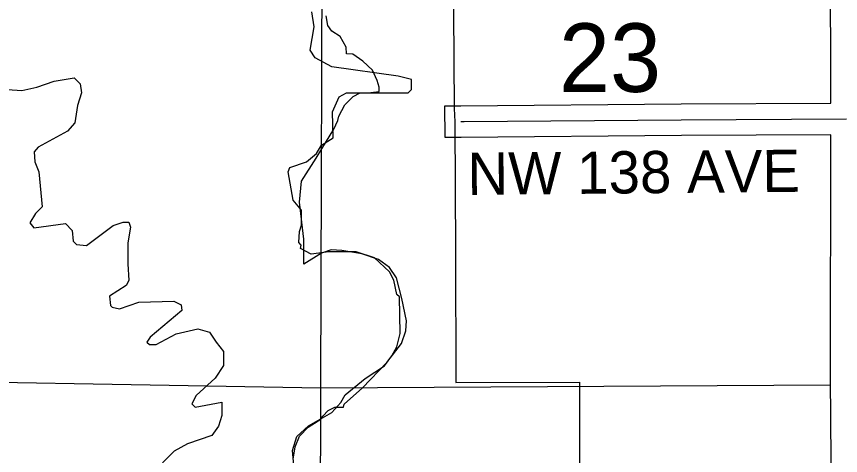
# Model space of a CAD drawing. Extents: x -1403959 to 81668, y -1400582 to 11018.
# Drawn here: x 6553.7 to 6704.7, y 9689.2 to 9769.7 of the extents above; entities that cross this region are included whole.
import ezdxf

# ---------------------------------------------------------------- set-up
doc = ezdxf.new("R2010")
doc.units = 0
for name, color, linetype in [('tdCiMapFrame', 7, 'Continuous'), ('tdCiRRCL', 7, 'Continuous'), ('tdCiSectLine', 7, 'Continuous'), ('tdCoCityStreetMajor', 7, 'Continuous'), ('tdCoSectLinePart', 7, 'Continuous'), ('tdCoSectNmbr', 7, 'Continuous'), ('tdCoSurfBitum', 7, 'Continuous')]:
    doc.layers.add(name, color=color, linetype=linetype)

msp = doc.modelspace()

# ---------------------------------------------------------------- linework, layer by layer
at = {"layer": 'tdCiMapFrame'}
for points in [[(6635.16, 9750.44), (6635.76, 9750.44)], [(6635.76, 9750.44), (6675.55, 9750.78), (6705.84, 9750.93)]]:
    msp.add_lwpolyline(points, dxfattribs=at)
at = {"layer": 'tdCiRRCL'}
for points in [[(6633.62, 9797.34), (6633.95, 9752.87), (6634.02, 9750.4), (6634.16, 9726.57), (6634.24, 9702.6), (6656.87, 9702.65), (6656.92, 9654.21), (6656.93, 9645.46), (6656.94, 9639.56), (6658.15, 9639.56), (6658.08, 9632.64), (6658.09, 9631.14), (6658.71, 9630.21), (6658.76, 9630.15), (6658.76, 9631.15), (6658.75, 9640.3), (6658.6, 9640.3), (6658.58, 9654.21), (6682.14, 9654.23), (6706.76, 9654.24)], [(6604.44, 9688.58), (6604.77, 9690.85), (6605.58, 9692.8), (6607.2, 9694.42), (6608.36, 9695.17), (6609.52, 9695.92), (6609.84, 9696.45), (6610.85, 9697.51), (6612.06, 9698.09), (6613.65, 9698.09), (6613.79, 9698.67), (6617.12, 9701.66), (6621.57, 9706.3), (6624.26, 9709.74), (6625.08, 9712.08), (6625.22, 9713.94), (6624.33, 9718), (6623.36, 9721.78), (6622.06, 9723.71), (6620.06, 9725.15), (6617.03, 9726.19), (6613.32, 9726.8), (6612.36, 9726.87), (6611.39, 9726.94), (6609.6, 9726.32), (6606.36, 9724.29), (6606.36, 9728.92), (6605.59, 9735.67), (6605.98, 9739.53), (6608.61, 9743.76), (6609.66, 9745.45), (6611.9, 9749.07), (6612.61, 9750.67), (6612.79, 9751.42), (6613.92, 9753.53), (6615.43, 9755.04), (6616.71, 9755.72), (6618.67, 9755.8), (6620.18, 9755.95), (6620.18, 9756.78), (6619.81, 9757.98), (6618.98, 9759.87), (6617.17, 9761.53), (6615.36, 9762.81), (6614.22, 9762.89), (6614.15, 9764.09), (6613.02, 9766.05), (6611.51, 9767.03), (6610.75, 9768.09), (6610.45, 9769.83)]]:
    msp.add_lwpolyline(points, dxfattribs=at)
at = {"layer": 'tdCiSectLine'}
msp.add_lwpolyline([(6703.7, 9606.54), (6702.89, 9703.36), (6702.89, 9703.38), (6702.89, 9703.38), (6702.93, 9748.01), (6675.57, 9747.88), (6635.19, 9747.53), (6632.29, 9747.51), (6632.24, 9753.31), (6635.14, 9753.34), (6675.53, 9753.68), (6675.54, 9753.68), (6702.93, 9753.82), (6702.92, 9781.7)], dxfattribs=at)
at = {"layer": 'tdCoCityStreetMajor'}
for points in [[(6609.5, 9701.61), (6609.78, 9798.41)], [(6512.12, 9703.33), (6609.5, 9701.61)], [(6609.32, 9626.77), (6609.5, 9701.61)], [(6609.5, 9701.61), (6702.87, 9702.16)]]:
    msp.add_lwpolyline(points, dxfattribs=at)
at = {"layer": 'tdCoSurfBitum'}
for points in [[(6604.61, 9686.76), (6604.31, 9690.12), (6605.08, 9692.71), (6607.22, 9694.69), (6611.5, 9697.13), (6613.18, 9698.95), (6613.95, 9700.33), (6617.62, 9703.37), (6621.14, 9705.65), (6622.51, 9707.48), (6623.43, 9709.16), (6624.05, 9711.6), (6623.91, 9718.32), (6623.45, 9718.78), (6622.85, 9721.37), (6622.09, 9722.9), (6619.35, 9725.5), (6615.99, 9726.58), (6610.95, 9726.59), (6607.74, 9726.14), (6605.76, 9727.21), (6605.91, 9727.82), (6605.46, 9728.28), (6605.61, 9730.27), (6605.92, 9731.49), (6605.93, 9734.23), (6604.4, 9736.07), (6603.5, 9741.26), (6603.81, 9742.02), (6606.86, 9743.09), (6608.7, 9744.61), (6609.62, 9746.13), (6611.76, 9747.5), (6611.61, 9752.23), (6612.84, 9754.98), (6614.22, 9755.74), (6625.52, 9755.71), (6626.13, 9756.32), (6626.13, 9758.15), (6623.69, 9758.77), (6611.48, 9760.48), (6608.43, 9762.16), (6607.51, 9763.54), (6608.29, 9767.81), (6607.83, 9770.56)], [(6552.07, 9756.34), (6554.67, 9756.18), (6557.42, 9756.79), (6560.63, 9757.85), (6564.29, 9758.45), (6565.36, 9757.38), (6565.66, 9755.7), (6564.89, 9753.41), (6564.43, 9750.21), (6563.05, 9748.68), (6557.7, 9745.79), (6556.94, 9744.88), (6557.08, 9743.05), (6557.84, 9741.21), (6558.44, 9734.8), (6557.22, 9733.58), (6556.14, 9731.91), (6556.91, 9730.99), (6562.71, 9731.74), (6563.93, 9730.51), (6564.08, 9728.53), (6564.69, 9727.92), (6566.52, 9727.76), (6571.41, 9731.41), (6573.25, 9732.02), (6574.32, 9732.02), (6574.62, 9731.1), (6574.15, 9728.2), (6574.15, 9724.38), (6574.29, 9721.33), (6573.83, 9720.42), (6570.77, 9718.44), (6570.92, 9716.76), (6571.23, 9716.45), (6572.6, 9716.15), (6576.12, 9717.36), (6582.53, 9717.5), (6583.9, 9716.88), (6584.05, 9715.81), (6578.24, 9710.94), (6577.63, 9710.03), (6578.09, 9709.57), (6579.31, 9709.57), (6582.98, 9711.54), (6586.95, 9712.45), (6589.08, 9711.83), (6590.3, 9710), (6591.67, 9708.32), (6591.67, 9705.72), (6590.14, 9703.43), (6586.62, 9700.24), (6585.85, 9698.71), (6586.46, 9698.1), (6591.35, 9699), (6591.34, 9696.56), (6590.73, 9694.58), (6589.5, 9692.9), (6585.07, 9691.39), (6582.63, 9690.02), (6580.48, 9687.89)]]:
    msp.add_lwpolyline(points, dxfattribs=at)

# ---------------------------------------------------------------- texts
at = {"layer": 'tdCoSectLinePart'}
msp.add_text('23', height=12.575, rotation=359.9914, dxfattribs=at).set_placement((6653.14, 9755.89))
at = {"layer": 'tdCoSectNmbr'}
msp.add_text('NW 138 AVE', height=7.738, rotation=0.5467, dxfattribs=at).set_placement((6636.39, 9737))

doc.saveas('drawing.dxf')
